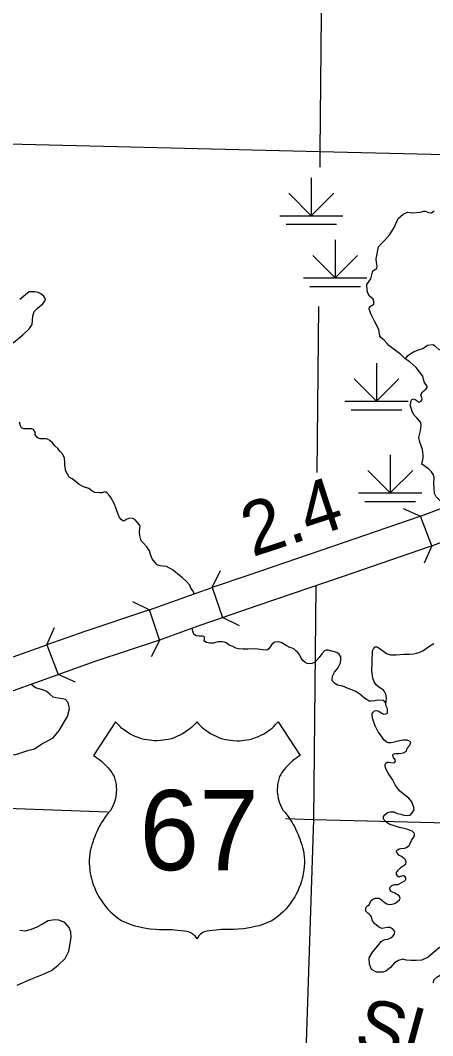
# Model space of a CAD drawing. Extents: x 8749 to 11879, y 13275 to 15339.
# Drawn here: x 10379.3 to 10444.5, y 13724.7 to 13885.3 of the extents above; entities that cross this region are included whole.
import ezdxf

# ---------------------------------------------------------------- set-up
doc = ezdxf.new("R2010")
doc.units = 0
for name, color, linetype in [('Level 15', 7, 'Continuous'), ('Level 22', 7, 'Continuous'), ('Level 35', 7, 'Continuous'), ('Level 37', 7, 'Continuous'), ('Level 44', 7, 'Continuous'), ('Level 48', 7, 'Continuous'), ('Level 5', 7, 'Continuous')]:
    doc.layers.add(name, color=color, linetype=linetype)

msp = doc.modelspace()

# ---------------------------------------------------------------- linework, layer by layer
at = {"layer": 'Level 15'}
for p, q in [((10444.35, 13802.22), (10444.35, 13802.22)), ((10401.35, 13787.34), (10401.34, 13787.34))]:
    msp.add_line(p, q, dxfattribs=at)
for points in [[(10442.56, 13806.89), (10448.03, 13808.95)], [(10444.35, 13802.22), (10442.56, 13806.89), (10442.31, 13806.8), (10428.81, 13802.13), (10415.29, 13797.53), (10409.67, 13795.61), (10411.28, 13790.88)], [(10444.35, 13802.22), (10449.72, 13804.25)], [(10411.28, 13790.88), (10416.91, 13792.8), (10430.43, 13797.4), (10444.01, 13802.09), (10444.35, 13802.22)], [(10399.75, 13792.07), (10406.06, 13794.37), (10409.67, 13795.61)], [(10401.34, 13787.34), (10399.75, 13792.07), (10389.54, 13788.67), (10383.53, 13786.53), (10385.31, 13781.86)], [(10401.35, 13787.34), (10407.73, 13789.66), (10411.28, 13790.88)], [(10373.6, 13783.02), (10376.57, 13784.06), (10383.53, 13786.53)], [(10385.31, 13781.86), (10391.16, 13783.94), (10401.35, 13787.34)], [(10375.24, 13778.3), (10378.23, 13779.34), (10385.31, 13781.86)]]:
    msp.add_lwpolyline(points, dxfattribs=at)
at = {"layer": 'Level 22'}
for points in [[(10407.22, 13774.34), (10406.96, 13774.05), (10406.71, 13773.79), (10406.42, 13773.52), (10406.11, 13773.26), (10405.82, 13773.03), (10405.45, 13772.77), (10405.07, 13772.53), (10404.63, 13772.29), (10404.06, 13772.03), (10403.64, 13771.86), (10403.15, 13771.7), (10402.7, 13771.59), (10402.3, 13771.5), (10401.86, 13771.44), (10401.47, 13771.4), (10400.92, 13771.37), (10400.48, 13771.38), (10400.09, 13771.4), (10399.73, 13771.44), (10399.36, 13771.5), (10398.89, 13771.59), (10398.46, 13771.7), (10397.93, 13771.87), (10397.49, 13772.05), (10397.08, 13772.24), (10396.71, 13772.43), (10396.37, 13772.63), (10395.98, 13772.88), (10395.63, 13773.14), (10395.33, 13773.39), (10395.08, 13773.61), (10394.82, 13773.87), (10394.56, 13774.13), (10394.35, 13774.37), (10390.89, 13769.02), (10391.14, 13768.87), (10391.43, 13768.68), (10391.71, 13768.48), (10392.08, 13768.19), (10392.38, 13767.93), (10392.64, 13767.69), (10392.91, 13767.42), (10393.19, 13767.11), (10393.38, 13766.87), (10393.58, 13766.62), (10393.78, 13766.35), (10393.97, 13766.06), (10394.14, 13765.72), (10394.28, 13765.3), (10394.38, 13764.89), (10394.46, 13764.44), (10394.5, 13764.03), (10394.51, 13763.64), (10394.5, 13763.27), (10394.48, 13762.97), (10394.43, 13762.61), (10394.36, 13762.26), (10394.27, 13761.89), (10394.16, 13761.57), (10394.02, 13761.2), (10393.79, 13760.73), (10393.56, 13760.36), (10393.28, 13760.02), (10392.95, 13759.59), (10392.67, 13759.21), (10392.41, 13758.82), (10392.18, 13758.45), (10391.98, 13758.12), (10391.81, 13757.8), (10391.61, 13757.43), (10391.4, 13756.99), (10391.21, 13756.56), (10391.08, 13756.25), (10390.93, 13755.84), (10390.76, 13755.34), (10390.63, 13754.93), (10390.5, 13754.47), (10390.39, 13753.95), (10390.31, 13753.48), (10390.25, 13752.99), (10390.22, 13752.46), (10390.22, 13751.96), (10390.24, 13751.47), (10390.3, 13750.89), (10390.39, 13750.35), (10390.48, 13749.94), (10390.57, 13749.58), (10390.69, 13749.17), (10390.85, 13748.66), (10391.08, 13748.04), (10391.28, 13747.59), (10391.51, 13747.12), (10391.76, 13746.67), (10392.08, 13746.14), (10392.42, 13745.66), (10392.75, 13745.24), (10393.12, 13744.81), (10393.6, 13744.31), (10394, 13743.93), (10394.42, 13743.58)], [(10407.22, 13774.34), (10407.49, 13774.05), (10407.74, 13773.79), (10408.02, 13773.52), (10408.33, 13773.26), (10408.63, 13773.03), (10408.99, 13772.77), (10409.38, 13772.53), (10409.82, 13772.29), (10410.38, 13772.03), (10410.81, 13771.86), (10411.3, 13771.7), (10411.74, 13771.59), (10412.15, 13771.5), (10412.58, 13771.44), (10412.98, 13771.4), (10413.52, 13771.37), (10413.97, 13771.38), (10414.35, 13771.4), (10414.72, 13771.44), (10415.09, 13771.5), (10415.56, 13771.59), (10415.99, 13771.7), (10416.51, 13771.87), (10416.96, 13772.05), (10417.36, 13772.24), (10417.74, 13772.43), (10418.08, 13772.63), (10418.46, 13772.88), (10418.81, 13773.14), (10419.11, 13773.39), (10419.37, 13773.61), (10419.63, 13773.87), (10419.88, 13774.13), (10420.09, 13774.37), (10423.55, 13769.02), (10423.31, 13768.87), (10423.01, 13768.68), (10422.73, 13768.48), (10422.36, 13768.19), (10422.06, 13767.93), (10421.8, 13767.69), (10421.53, 13767.42), (10421.26, 13767.11), (10421.06, 13766.87), (10420.87, 13766.62), (10420.67, 13766.35), (10420.48, 13766.06), (10420.3, 13765.72), (10420.17, 13765.3), (10420.06, 13764.89), (10419.99, 13764.44), (10419.95, 13764.03), (10419.93, 13763.64), (10419.94, 13763.27), (10419.97, 13762.97), (10420.02, 13762.61), (10420.08, 13762.26), (10420.18, 13761.89), (10420.28, 13761.57), (10420.43, 13761.2), (10420.65, 13760.73), (10420.88, 13760.36), (10421.16, 13760.02), (10421.5, 13759.59), (10421.77, 13759.21), (10422.03, 13758.82), (10422.27, 13758.45), (10422.46, 13758.12), (10422.64, 13757.8), (10422.83, 13757.43), (10423.04, 13756.99), (10423.23, 13756.56), (10423.36, 13756.25), (10423.51, 13755.84), (10423.68, 13755.34), (10423.82, 13754.93), (10423.94, 13754.47), (10424.06, 13753.95), (10424.14, 13753.48), (10424.19, 13752.99), (10424.22, 13752.46), (10424.23, 13751.96), (10424.2, 13751.47), (10424.14, 13750.89), (10424.05, 13750.35), (10423.96, 13749.94), (10423.87, 13749.58), (10423.75, 13749.17), (10423.59, 13748.66), (10423.36, 13748.04), (10423.17, 13747.59), (10422.94, 13747.12), (10422.69, 13746.67), (10422.36, 13746.14), (10422.02, 13745.66), (10421.7, 13745.24), (10421.33, 13744.81), (10420.85, 13744.31), (10420.44, 13743.93), (10420.03, 13743.58)], [(10394.42, 13743.58), (10394.85, 13743.25), (10395.38, 13742.91), (10396.03, 13742.62), (10396.8, 13742.33), (10397.42, 13742.12), (10397.99, 13741.97), (10398.62, 13741.82), (10399.22, 13741.71), (10399.86, 13741.62), (10400.67, 13741.55), (10401.29, 13741.53), (10401.82, 13741.53), (10402.34, 13741.53), (10402.85, 13741.51), (10403.34, 13741.49), (10403.77, 13741.46), (10404.19, 13741.42), (10404.72, 13741.37), (10405.25, 13741.3), (10405.57, 13741.26), (10405.83, 13741.21), (10406.14, 13741.08), (10406.32, 13740.98), (10406.48, 13740.87), (10406.7, 13740.7), (10406.9, 13740.49), (10407.07, 13740.27), (10407.22, 13740.02)], [(10420.03, 13743.58), (10419.59, 13743.25), (10419.07, 13742.91), (10418.41, 13742.62), (10417.65, 13742.33), (10417.02, 13742.12), (10416.46, 13741.97), (10415.82, 13741.82), (10415.23, 13741.71), (10414.58, 13741.62), (10413.77, 13741.55), (10413.15, 13741.53), (10412.62, 13741.53), (10412.11, 13741.53), (10411.59, 13741.51), (10411.1, 13741.49), (10410.68, 13741.46), (10410.26, 13741.42), (10409.72, 13741.37), (10409.19, 13741.3), (10408.88, 13741.26), (10408.62, 13741.21), (10408.3, 13741.08), (10408.12, 13740.98), (10407.97, 13740.87), (10407.75, 13740.7), (10407.54, 13740.49), (10407.37, 13740.27), (10407.22, 13740.02)]]:
    msp.add_lwpolyline(points, dxfattribs=at)
at = {"layer": 'Level 35'}
for points in [[(10434.13, 13842.57), (10434.1, 13843.57), (10434.7, 13844.42), (10435.03, 13845.7), (10435.65, 13846.1), (10435.73, 13846.52), (10435.6, 13847.02), (10435.58, 13847.62), (10435.93, 13849.52), (10436.43, 13850.02), (10436.92, 13850.57), (10437.75, 13851.47), (10438.42, 13852.57), (10439.02, 13853.99), (10439.85, 13854.67), (10440.54, 13854.97), (10441.39, 13854.87), (10442.57, 13854.97), (10443.07, 13855.17), (10443.32, 13855.17), (10443.84, 13854.92), (10444.29, 13854.89), (10444.71, 13855.19)], [(10443.65, 13827.25), (10443.62, 13827.45), (10443.42, 13827.75), (10443.17, 13828.15), (10442.97, 13829.05), (10442.25, 13829.92), (10441.87, 13830.4), (10440.9, 13831.32), (10440.15, 13831.8), (10439.48, 13832.47), (10438.83, 13832.95), (10437.58, 13833.9), (10437.33, 13834.22), (10436.85, 13834.72), (10436.33, 13835.15), (10436.13, 13835.45), (10435.98, 13836.45), (10435.33, 13837.74), (10434.78, 13838.82), (10434.46, 13839.67), (10434.53, 13840.02), (10434.76, 13840.17), (10435.18, 13840.44), (10435.21, 13840.87), (10435.08, 13841.22), (10434.53, 13841.72), (10434.31, 13842.07), (10434.13, 13842.57)], [(10378.19, 13834.31), (10379.71, 13835.58), (10380.76, 13836.61), (10381.19, 13837.21), (10381.29, 13838.53), (10381.53, 13839.26), (10382.03, 13839.78), (10382.88, 13840.51), (10383.16, 13840.86), (10383.28, 13841.08), (10383.21, 13841.45), (10383.03, 13841.68), (10382.56, 13842.08), (10382.13, 13842.3), (10381.63, 13842.4), (10381.31, 13842.4), (10380.74, 13842.38), (10379.24, 13841.2)], [(10448.18, 13835.04), (10447.39, 13834.57), (10447.04, 13834.24), (10446.81, 13833.74), (10446.36, 13833.37), (10445.84, 13833.12), (10445.49, 13833.29), (10445.01, 13833.69), (10444.56, 13834.02), (10443.67, 13833.92), (10442.94, 13833.37), (10442.17, 13833.17), (10441.49, 13832.84), (10440.4, 13832.17), (10440.15, 13831.8)], [(10442.8, 13815.13), (10443.02, 13816.15), (10443.02, 13816.6), (10442.87, 13817.47), (10442.47, 13818.62), (10442.3, 13819.35), (10442.55, 13820.42), (10442.7, 13821.24), (10442.62, 13821.72), (10441.97, 13822.44), (10441.57, 13822.87), (10441.27, 13823.47), (10441, 13824.34), (10441.07, 13825.02), (10441.22, 13825.34), (10441.45, 13825.47), (10441.72, 13825.34), (10442.37, 13824.92), (10442.7, 13825.09), (10442.82, 13825.44), (10442.65, 13826.12), (10442.87, 13826.59), (10443.4, 13827), (10443.65, 13827.25)], [(10386.36, 13815.35), (10386.33, 13816.12), (10385.93, 13816.79), (10385.63, 13817.14), (10385.26, 13817.62), (10384.76, 13818.02), (10384.41, 13818.49), (10383.98, 13818.89), (10383.61, 13819.07), (10383.39, 13819.14), (10383.16, 13819.14), (10382.84, 13819.14), (10382.46, 13819.12), (10382.19, 13819.22), (10381.94, 13819.42), (10381.69, 13819.84), (10381.66, 13820.19), (10381.41, 13820.59), (10381.14, 13820.74), (10380.31, 13820.74), (10379.89, 13820.71), (10379.49, 13820.89), (10379.34, 13821.19), (10379.17, 13821.76)], [(10398.43, 13803.02), (10398.22, 13803.86), (10398.17, 13804.36), (10398.22, 13804.93), (10398.26, 13805.38), (10397.84, 13805.91), (10397.49, 13806.33), (10397.09, 13806.51), (10396.57, 13806.61), (10396.07, 13806.38), (10395.77, 13806.16), (10395.54, 13806.18), (10395.24, 13806.36), (10395.02, 13806.71), (10394.74, 13807.33), (10394.22, 13808.81), (10393.65, 13809.86), (10393.35, 13810.23), (10393.1, 13810.51), (10392.82, 13810.71), (10392.6, 13810.73), (10392.25, 13810.58), (10391.85, 13810.58), (10391.12, 13810.66), (10390.63, 13810.93), (10390.13, 13811.26), (10389.33, 13811.53), (10388.63, 13811.93), (10388, 13812.46), (10387.5, 13812.81), (10387.06, 13813.08), (10386.51, 13814.01), (10386.38, 13814.93), (10386.36, 13815.35)], [(10446.51, 13808.38), (10446.27, 13808.71), (10445.57, 13809.41), (10445.05, 13809.94), (10444.8, 13810.49), (10444.72, 13811.34), (10444.7, 13812.14), (10444.72, 13812.99), (10444.62, 13813.44), (10444.3, 13813.89), (10443.83, 13814.39), (10442.8, 13815.13)], [(10406.79, 13794.62), (10406.65, 13795.03), (10406.3, 13795.5), (10406.1, 13796), (10405.53, 13796.6), (10404.88, 13797.18), (10404.2, 13797.75), (10403.48, 13798.35), (10402.45, 13798.92), (10401.88, 13798.97), (10401.43, 13799.05), (10400.98, 13799.22), (10400.58, 13799.65), (10400.16, 13800.15), (10399.91, 13800.85), (10399.76, 13801.4), (10399.33, 13802.07), (10398.76, 13802.67), (10398.43, 13803.02)], [(10406.55, 13788.89), (10406.49, 13789.21)], [(10415.27, 13785.85), (10414.55, 13785.87), (10413.81, 13785.94), (10413.38, 13786.04), (10412.93, 13786.27), (10412.35, 13786.5), (10411.85, 13786.84), (10411.55, 13786.95), (10411.22, 13787), (10410.87, 13787.02), (10410.57, 13787.02), (10410.17, 13786.89), (10409.84, 13786.82), (10409.29, 13786.79), (10408.76, 13786.89), (10408.48, 13787.07), (10408.4, 13787.25), (10408.46, 13787.51), (10408.43, 13787.75), (10408.32, 13787.85), (10408.13, 13787.91), (10407.9, 13787.91), (10407.52, 13787.9), (10407.12, 13787.95), (10406.94, 13788.07), (10406.75, 13788.26), (10406.55, 13788.89)], [(10421.93, 13786.12), (10421.33, 13786.45), (10420.55, 13786.9), (10420.12, 13787.02), (10419.57, 13786.99), (10419.15, 13786.69), (10418.7, 13786.07), (10418.59, 13785.89), (10418.37, 13785.74), (10418.11, 13785.72), (10417.68, 13785.75), (10416.88, 13785.85), (10416.26, 13785.91), (10415.27, 13785.85)], [(10434.9, 13782.39), (10434.96, 13783.81), (10434.99, 13785.59), (10435.16, 13785.91), (10435.41, 13786.24), (10435.71, 13786.24), (10436.06, 13786.01), (10436.59, 13785.64), (10437.19, 13785.16), (10437.84, 13784.99), (10438.73, 13784.99), (10439.93, 13785.06), (10440.83, 13785.09), (10441.46, 13785.11), (10441.93, 13785.24), (10442.48, 13785.39), (10442.95, 13785.59), (10444.03, 13786.41), (10444.68, 13786.76)], [(10425.83, 13783.74), (10425.39, 13783.58), (10425.12, 13783.55), (10424.68, 13783.6), (10424.29, 13783.8), (10423.96, 13784.06), (10423.69, 13784.42), (10423.44, 13785.02), (10423.13, 13785.41), (10422.89, 13785.62), (10422.57, 13785.92), (10422.27, 13786.02), (10421.93, 13786.12)], [(10428.62, 13780.87), (10428.65, 13781.58), (10428.96, 13782.21), (10429.3, 13782.6), (10429.52, 13782.85), (10429.71, 13783.28), (10429.91, 13783.71), (10430, 13784.25), (10429.97, 13784.67), (10429.7, 13785.05), (10429.35, 13785.34), (10427.96, 13785.71), (10427.69, 13785.7), (10427.39, 13785.6), (10426.97, 13785.11), (10426.54, 13784.52), (10426.16, 13784.06), (10425.83, 13783.74)], [(10437.09, 13777.2), (10437.19, 13778.18), (10437.1, 13778.75), (10436.87, 13779.15), (10436.71, 13779.36), (10436.25, 13779.71), (10436.01, 13779.87), (10435.59, 13780.23), (10435.26, 13780.7), (10435.06, 13781.28), (10434.98, 13781.68), (10434.9, 13782.39)], [(10386.01, 13778.02), (10384.93, 13778.16), (10384.51, 13778.28), (10383.98, 13778.73), (10383.41, 13779.21), (10382.66, 13779.46), (10381.74, 13779.76), (10380.97, 13780.32)], [(10437.16, 13776.84), (10437.09, 13777.2), (10436.97, 13777.46), (10436.69, 13777.72), (10435.85, 13777.78), (10435.35, 13777.67), (10434.79, 13777.63), (10434.46, 13777.66), (10433.8, 13778.08), (10432.92, 13778.8), (10432.27, 13779.21), (10431.14, 13779.65), (10430.28, 13780), (10429.48, 13780.17), (10429.06, 13780.42), (10428.77, 13780.68), (10428.62, 13780.87)], [(10374.42, 13768.12), (10375.87, 13768.87), (10376.92, 13769.02), (10378.64, 13769.22), (10380.51, 13769.82), (10381.54, 13770.12), (10382.59, 13770.77), (10384.53, 13771.82), (10385.46, 13772.97), (10386.78, 13775.2), (10387.08, 13776.44), (10386.88, 13777.44), (10386.46, 13777.89), (10386.01, 13778.02)], [(10435.91, 13772.81), (10435.5, 13773.5), (10435.48, 13773.59), (10435.04, 13774.79), (10434.96, 13775.35), (10434.96, 13775.66), (10435.08, 13775.9), (10435.29, 13776.09), (10435.58, 13776.15), (10435.82, 13776.13), (10436.06, 13776.01), (10436.45, 13775.74), (10436.76, 13775.59), (10437.12, 13775.61), (10437.34, 13775.75), (10437.37, 13776.03), (10437.34, 13776.41), (10437.16, 13776.84)], [(10438.13, 13765.26), (10437.48, 13766.27), (10437.17, 13766.85), (10436.99, 13767.28), (10436.99, 13767.58), (10437.09, 13767.85), (10437.29, 13768), (10437.52, 13768), (10437.87, 13767.91), (10438.31, 13767.9), (10438.53, 13767.98), (10438.64, 13768.15), (10438.59, 13768.33), (10438.32, 13768.73), (10438.18, 13769.06), (10438.27, 13769.24), (10438.59, 13769.34), (10439.2, 13769.34), (10439.88, 13769.44), (10440.38, 13769.7), (10440.48, 13770.21), (10440.88, 13770.7), (10441.05, 13771.11), (10440.85, 13771.33), (10440.45, 13771.46), (10439.82, 13771.45), (10439.02, 13771.33), (10438.4, 13771.14), (10437.96, 13771.06), (10437.54, 13771.06), (10437.18, 13771.16), (10436.78, 13771.54), (10436.41, 13772.1), (10435.91, 13772.81)], [(10437.07, 13758.59), (10436.74, 13758.97), (10436.71, 13759.4), (10436.94, 13759.68), (10437.36, 13760.02), (10437.78, 13760.14), (10438.34, 13760.13), (10438.89, 13759.88), (10439.47, 13759.74), (10439.95, 13759.59), (10440.46, 13759.57), (10440.96, 13759.62), (10441.28, 13759.98), (10441.55, 13760.42), (10441.54, 13760.83), (10441.19, 13761.69), (10440.74, 13762.28), (10440.1, 13762.77), (10439.24, 13763.47), (10438.59, 13764.4), (10438.13, 13765.26)], [(10439.99, 13751.7), (10440.24, 13751.92), (10440.31, 13752.18), (10440.19, 13752.53), (10439.99, 13752.77), (10439.55, 13753.04), (10439.17, 13753.27), (10438.92, 13753.57), (10438.8, 13753.74), (10438.79, 13753.97), (10438.92, 13754.13), (10439.2, 13754.29), (10439.48, 13754.32), (10440.03, 13754.37), (10440.34, 13754.47), (10440.79, 13754.82), (10440.91, 13755.04), (10441.13, 13755.59), (10441.39, 13755.9), (10441.63, 13756.35), (10441.61, 13756.68), (10441.24, 13757.06), (10440.96, 13757.2), (10440.43, 13757.38), (10439.28, 13757.63), (10438.23, 13757.95), (10437.63, 13758.18), (10437.26, 13758.43), (10437.07, 13758.59)], [(10439.34, 13746.45), (10439.19, 13746.82), (10438.54, 13747.27), (10437.88, 13747.54), (10437.72, 13747.94), (10437.76, 13748.19), (10438.06, 13748.5), (10438.52, 13748.64), (10439.04, 13748.66), (10439.42, 13748.87), (10439.76, 13749.04), (10440.14, 13749.26), (10440.25, 13749.5), (10440.28, 13749.67), (10440.16, 13749.87), (10439.91, 13750.02), (10439.76, 13750.01), (10439.44, 13749.92), (10439.23, 13749.82), (10438.97, 13749.94), (10438.76, 13750.19), (10438.78, 13750.54), (10439.11, 13750.95), (10439.29, 13751.19), (10439.51, 13751.39), (10439.82, 13751.59), (10439.99, 13751.7)], [(10436.37, 13739.6), (10436.65, 13739.85), (10437, 13739.95), (10437.4, 13740.01), (10437.87, 13740.21), (10438.21, 13740.46), (10438.48, 13740.76), (10438.51, 13741.21), (10438.28, 13741.51), (10437.8, 13741.81), (10437.35, 13741.84), (10436.8, 13741.71), (10436.44, 13741.69), (10436.02, 13741.86), (10435.95, 13741.92), (10435.31, 13742.44), (10435.01, 13742.9), (10434.9, 13743.24), (10434.84, 13743.5), (10434.71, 13743.7), (10434.5, 13743.89), (10434.24, 13744.1), (10433.96, 13744.44), (10433.94, 13744.79), (10434, 13745.05), (10434.2, 13745.26), (10434.44, 13745.44), (10434.61, 13745.79), (10434.74, 13746.05), (10435.05, 13746.34), (10435.44, 13746.47), (10436.02, 13746.46), (10436.41, 13746.19), (10436.83, 13745.82), (10437.25, 13745.57), (10437.63, 13745.49), (10438.12, 13745.5), (10438.46, 13745.62), (10438.88, 13745.9), (10439.26, 13746.19), (10439.34, 13746.45)], [(10387.01, 13738.1), (10387.38, 13740.23), (10387.33, 13741.08), (10387.03, 13741.85), (10386.38, 13742.6), (10385.43, 13743), (10384.76, 13743.02), (10383.73, 13742.87), (10382.84, 13742.37), (10381.96, 13741.87), (10381.04, 13741.52), (10380.04, 13741.25), (10379.27, 13741.35)], [(10439.76, 13736.8), (10439.11, 13736.63), (10438.49, 13736.25), (10437.84, 13735.53), (10437.12, 13734.93), (10436.64, 13734.78), (10435.62, 13734.76), (10434.84, 13735.21), (10434.5, 13736.05), (10434.45, 13737.05), (10434.99, 13737.95), (10435.84, 13738.95), (10436.37, 13739.6)], [(10444.65, 13733.06), (10444.7, 13733.53), (10445.15, 13733.98), (10445.67, 13734.28), (10446.45, 13734.78), (10447.02, 13735.36), (10447.67, 13736.2), (10448.3, 13736.9), (10448.3, 13737.68), (10448.27, 13738.23), (10447.7, 13738.78), (10446.9, 13739), (10446.2, 13738.93), (10445.5, 13738.63), (10444.6, 13737.83), (10443.78, 13737.15), (10442.8, 13736.68), (10441.88, 13736.6), (10441.06, 13736.63), (10440.36, 13736.65), (10439.76, 13736.8)], [(10378.82, 13732.7), (10380.96, 13733.65), (10382.84, 13734.42), (10384.26, 13735.05), (10385.33, 13735.87), (10386.41, 13736.95), (10387.01, 13738.1)]]:
    msp.add_lwpolyline(points, dxfattribs=at)
at = {"layer": 'Level 37'}
for points in [[(10439.82, 13808.11), (10442.56, 13806.89)], [(10444.35, 13802.22), (10443.13, 13799.48)], [(10409.67, 13795.61), (10410.99, 13798.3)], [(10397.07, 13793.41), (10399.75, 13792.08)], [(10413.98, 13789.55), (10411.28, 13790.88)], [(10383.52, 13786.53), (10384.75, 13789.27)], [(10401.35, 13787.34), (10400.01, 13784.65)], [(10388.05, 13780.64), (10385.31, 13781.86)]]:
    msp.add_lwpolyline(points, dxfattribs=at)
at = {"layer": 'Level 44'}
for p, q in [((10425.32, 13860.43), (10425.32, 13854.43)), ((10425.32, 13854.43), (10421.79, 13857.97)), ((10425.32, 13854.43), (10428.86, 13857.97)), ((10420.32, 13854.43), (10430.32, 13854.43)), ((10421.32, 13853.07), (10429.32, 13853.07)), ((10429.09, 13850.6), (10429.09, 13844.6)), ((10429.09, 13844.6), (10425.55, 13848.13)), ((10429.09, 13844.6), (10432.63, 13848.13)), ((10424.09, 13844.6), (10434.09, 13844.6)), ((10425.09, 13843.23), (10433.09, 13843.23)), ((10435.61, 13831.09), (10435.61, 13825.09)), ((10435.61, 13825.09), (10432.07, 13828.63)), ((10435.61, 13825.09), (10439.14, 13828.63)), ((10430.61, 13825.09), (10440.61, 13825.09)), ((10431.61, 13823.73), (10439.61, 13823.73)), ((10437.8, 13816.6), (10437.8, 13810.6)), ((10437.8, 13810.6), (10434.27, 13814.13)), ((10437.8, 13810.6), (10441.34, 13814.13)), ((10432.8, 13810.6), (10442.8, 13810.6)), ((10433.8, 13809.24), (10441.8, 13809.24))]:
    msp.add_line(p, q, dxfattribs=at)
at = {"layer": 'Level 5'}
for points in [[(10427.08, 13908.01), (10426.69, 13864.57)], [(10371.03, 13865.96), (10426.69, 13864.57)], [(10426.69, 13864.57), (10426.67, 13862.09)], [(10426.69, 13864.57), (10468.46, 13863.59), (10499.82, 13863.04)], [(10426.45, 13840.07), (10426.2, 13813.8)], [(10426.02, 13795.9), (10425.67, 13758.93)], [(10329.6, 13762.46), (10393.1, 13760.13)], [(10421.25, 13759.1), (10425.67, 13758.93)], [(10425.67, 13758.93), (10422.16, 13653.16)], [(10425.67, 13758.93), (10453.23, 13758.25)]]:
    msp.add_lwpolyline(points, dxfattribs=at)

# ---------------------------------------------------------------- texts
at = {"layer": 'Level 22'}
msp.add_text('67', height=12.672, dxfattribs=at).set_placement((10398.15, 13750.9))
at = {"layer": 'Level 35'}
msp.add_text('Sl.', height=8.448, rotation=344.7907, dxfattribs=at).set_placement((10431.77, 13722.82))
at = {"layer": 'Level 48'}
msp.add_text('2.4', height=8.448, rotation=18.188, dxfattribs=at).set_placement((10416, 13800.4))

doc.saveas('drawing.dxf')
